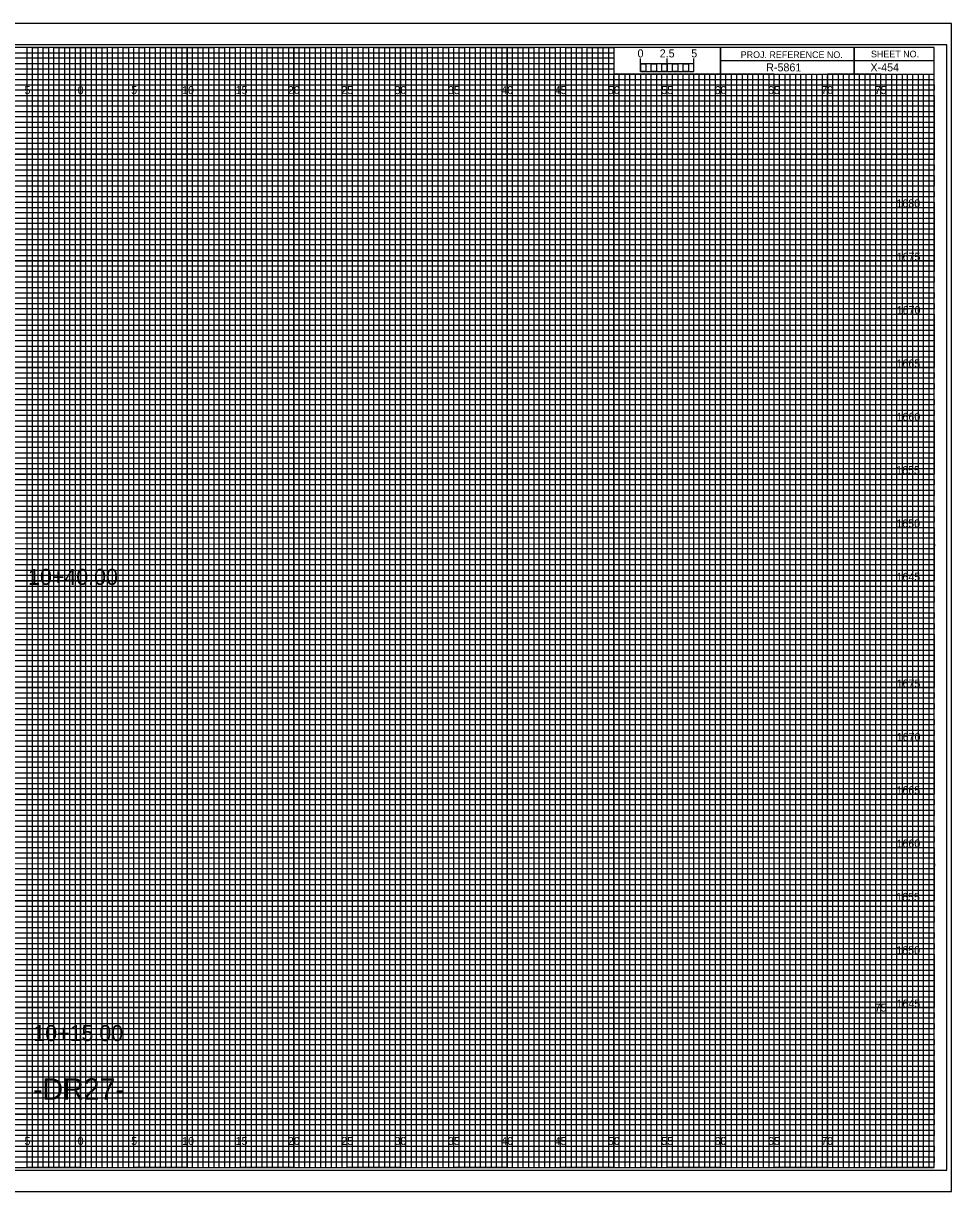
# Model space of a CAD drawing. Extents: x -7 to 162, y -2 to 217.
# Drawn here: x 74.6 to 161.7, y -2.3 to 107.3 of the extents above; entities that cross this region are included whole.
import ezdxf

# ---------------------------------------------------------------- set-up
doc = ezdxf.new("R2010")
doc.units = 0
for name, color, linetype in [('Prop Horizontal Alignment', 7, 'Continuous'), ('Prop XS Alignment Label', 7, 'Continuous'), ('Prop XS Bar Scale Labels', 7, 'Continuous'), ('Prop XS Gore Control Minimum', 7, 'Continuous'), ('Prop XS Project Number', 7, 'Continuous'), ('Prop XS Sheet Number', 7, 'Continuous'), ('Raster_Level_0', 7, 'Continuous'), ('Scratch_Level_3', 7, 'Continuous'), ('Sheet Cross Section CELL', 7, 'Continuous'), ('Sheet Cross Section Grid Middle CELL', 7, 'Continuous'), ('Sheet Cross Section Grid Minor 1 CELL', 7, 'Continuous'), ('Sheet Cross Section Grid Minor 2 CELL', 7, 'Continuous'), ('Sheet Cross Section Scale CELL', 7, 'Continuous'), ('Sheet Cutting Line CELL', 7, 'Continuous'), ('Sheet DOT Grid CELL', 7, 'Continuous'), ('Sheet Plot Border Inside CELL', 7, 'Continuous'), ('Sheet Plot Border Outside CELL', 7, 'Continuous')]:
    doc.layers.add(name, color=color, linetype=linetype)

msp = doc.modelspace()

# ---------------------------------------------------------------- linework, layer by layer
at = {"layer": 'Prop XS Gore Control Minimum'}
for p, q in [((75, 105), (70, 105)), ((75, 0), (75, 105)), ((85, 105), (80, 105)), ((80, 105), (80, 0)), ((85, 0), (85, 105)), ((95, 105), (90, 105)), ((90, 105), (90, 0)), ((95, 0), (95, 105)), ((105, 105), (100, 105)), ((100, 105), (100, 0)), ((105, 0), (105, 105)), ((115, 105), (110, 105)), ((110, 105), (110, 0)), ((115, 0), (115, 105)), ((125, 105), (120, 105)), ((120, 105), (120, 0)), ((125, 0), (125, 105)), ((130, 105), (130, 0)), ((135, 0), (135, 102.5)), ((145, 102.5), (140, 102.5)), ((140, 102.5), (140, 0)), ((145, 0), (145, 102.5)), ((155, 102.5), (150, 102.5)), ((150, 102.5), (150, 0)), ((155, 0), (155, 102.5)), ((80, 0), (75, 0)), ((90, 0), (85, 0)), ((100, 0), (95, 0)), ((110, 0), (105, 0)), ((120, 0), (115, 0)), ((130, 0), (125, 0)), ((140, 0), (135, 0)), ((150, 0), (145, 0)), ((160, 0), (155, 0)), ((160, 0), (160, 0))]:
    msp.add_line(p, q, dxfattribs=at)
for points in [[(0, 100), (160, 100), (160, 95), (0, 95)], [(0, 90), (160, 90), (160, 85), (0, 85)], [(0, 80), (160, 80), (160, 75), (0, 75)], [(0, 70), (160, 70), (160, 65), (0, 65)], [(0, 60), (160, 60), (160, 55), (0, 55)], [(0, 50), (160, 50), (160, 45), (0, 45)], [(0, 40), (160, 40), (160, 35), (0, 35)], [(0, 30), (160, 30), (160, 25), (0, 25)], [(0, 20), (160, 20), (160, 15), (0, 15)], [(0, 10), (160, 10), (160, 5), (0, 5)]]:
    msp.add_lwpolyline(points, dxfattribs=at)
at = {"layer": 'Sheet Cross Section CELL'}
for p, q in [((152.5, 105), (152.5, 102.5)), ((152.5, 102.5), (152.5, 105)), ((160, 103.75), (140, 103.75)), ((140, 103.75), (140, 102.5)), ((140, 102.5), (160, 102.5))]:
    msp.add_line(p, q, dxfattribs=at)
for points in [[(160, 105), (0, 105), (0, 0), (160, 0)], [(140, 105), (130, 105), (130, 102.52), (140, 102.52)], [(160, 105), (140, 105), (140, 102.5), (160, 102.5)]]:
    msp.add_lwpolyline(points, close=True, dxfattribs=at)
at = {"layer": 'Sheet Cross Section Grid Middle CELL'}
for points in [[(72.5, 0), (77.5, 0), (77.5, 105), (82.5, 105), (82.5, 0), (87.5, 0), (87.5, 105), (92.5, 105), (92.5, 0), (97.5, 0), (97.5, 105), (102.5, 105), (102.5, 0), (107.5, 0), (107.5, 105), (112.5, 105), (112.5, 0), (117.5, 0), (117.5, 105), (122.5, 105), (122.5, 0), (127.5, 0), (127.5, 105), (129.97, 105), (130, 105), (130, 102.5), (132.5, 102.5), (132.5, 0), (137.5, 0), (137.5, 102.5), (142.5, 102.5), (142.5, 0), (147.5, 0), (147.5, 102.5), (152.5, 102.5), (152.5, 0), (157.5, 0), (157.5, 102.5)], [(0, 102.5), (137.5, 102.5)], [(0, 92.5), (160, 92.5), (160, 97.5), (0, 97.5)], [(0, 82.5), (160, 82.5), (160, 87.5), (0, 87.5)], [(0, 72.5), (160, 72.5), (160, 77.5), (0, 77.5)], [(0, 62.5), (160, 62.5), (160, 67.5), (0, 67.5)], [(0, 52.5), (160, 52.5), (160, 57.5), (0, 57.5)], [(0, 42.5), (160, 42.5), (160, 47.5), (0, 47.5)], [(0, 32.5), (160, 32.5), (160, 37.5), (0, 37.5)], [(0, 22.5), (160, 22.5), (160, 27.5), (0, 27.5)], [(0, 12.5), (160, 12.5), (160, 17.5), (0, 17.5)], [(0, 2.5), (160, 2.5), (160, 7.5), (0, 7.5)]]:
    msp.add_lwpolyline(points, dxfattribs=at)
at = {"layer": 'Sheet Cross Section Grid Minor 1 CELL'}
for p, q in [((0, 104.5), (130, 104.5)), ((130, 104.5), (130, 103.99)), ((130, 103.99), (0, 103.99)), ((0, 103.5), (130, 103.5)), ((130, 102.95), (0, 102.95)), ((130, 103.5), (130, 102.95)), ((0, 102), (160, 102))]:
    msp.add_line(p, q, dxfattribs=at)
for points in [[(0, 101.5), (135, 101.5), (160, 101.5), (160, 101), (0, 101)], [(0, 100.5), (160, 100.5), (160, 99.5), (0, 99.5)], [(0, 99), (160, 99), (160, 98.5), (0, 98.49)], [(0, 98), (160, 98), (160, 97), (0, 97)], [(0, 96.5), (160, 96.5), (160, 96), (0, 96)], [(0, 95.5), (160, 95.5), (160, 94.5), (0, 94.5)], [(0, 94), (160, 94), (160, 93.5), (0, 93.5)], [(0, 93), (160, 93), (160, 92), (0, 92)], [(0, 91.5), (160, 91.5), (160, 91), (0, 91)], [(0, 90.5), (160, 90.5), (160, 89.5), (0, 89.5)], [(0, 89), (160, 89), (160, 88.5), (0, 88.5)], [(0, 88), (160, 88), (160, 86.98), (160, 86.5), (160, 86), (0, 86)], [(0, 87), (160, 87), (160, 86.5), (0, 86.5)], [(0, 85.5), (160, 85.5), (160, 84.5), (0, 84.52)], [(0, 84.52), (160, 84.5), (160, 84), (0, 84)], [(0, 83.5), (160, 83.5), (160, 83), (0, 83)], [(0, 82), (160, 82), (160, 81.5), (0, 81.5)], [(0, 81), (160, 81), (160, 80.5), (0, 80.5)], [(-0.04, 79.45), (160, 79.45), (160, 78.94), (-0.04, 78.94)], [(0, 78.5), (160, 78.5), (160, 78), (0, 78)], [(0, 77), (160, 77), (160, 76.5), (0, 76.5)], [(0, 76), (160, 76), (160, 75.5), (0, 75.5)], [(0, 74.5), (160, 74.5), (160, 74), (0, 74)], [(0, 73.5), (160, 73.5), (160, 73), (0, 73)], [(0, 72), (160, 72), (160, 71.5), (0, 71.5)], [(0, 71), (160, 71), (160, 70.5), (0, 70.5)], [(0, 69.5), (160, 69.5), (160, 68.99), (0, 69)], [(0, 68.5), (160, 68.5), (160, 68), (0, 68)], [(0, 67), (160, 67), (160, 66.5), (0, 66.5)], [(0, 66), (160, 66), (160, 65.5), (0, 65.5)], [(0, 64.5), (160, 64.5), (160, 64), (0, 64)], [(0, 63.5), (160, 63.5), (160, 63), (0, 63)], [(0, 62), (160, 62), (160, 61.5), (0, 61.5)], [(0, 61), (160, 61), (160, 60.5), (0, 60.5)], [(0, 59.5), (160, 59.5), (160, 59), (0, 59)], [(0, 58.5), (160.03, 58.45), (160, 58), (0, 58)], [(0, 57), (160, 57), (160, 56.5), (0, 56.5)], [(0, 56), (160, 56), (160, 55.5), (0, 55.5)], [(0, 54.5), (160, 54.5), (160, 54), (0, 54)], [(0, 53.5), (160, 53.5), (160, 53), (0, 53)], [(0, 52), (160, 52), (160, 51.5), (0, 51.5)], [(0, 51), (160, 51), (160, 50.5), (0, 50.5)], [(0, 49.5), (160, 49.5), (160, 49), (0, 49)], [(0, 48.5), (160, 48.5), (160, 48), (0, 48)], [(0, 47), (160, 47), (160, 46.5), (0, 46.5)], [(0, 46), (160, 46), (160, 45.5), (0, 45.5)], [(0, 44.5), (160, 44.5), (160, 44), (0, 44)], [(0, 43.5), (160, 43.5), (160, 43), (0, 43)], [(0, 42), (160, 42), (160, 41.5), (0, 41.5)], [(0, 41), (160, 41), (160, 40.5), (0, 40.5)], [(0, 39.5), (160, 39.5), (160, 38.99), (0, 39)], [(0, 38.5), (160, 38.5), (160, 38), (0, 38)], [(0, 37), (160, 37), (160, 36.5), (0, 36.5)], [(0, 36), (160, 36), (160, 35.5), (0, 35.5)], [(0, 34.5), (160, 34.5), (160, 34), (0, 34)], [(0, 33.5), (160, 33.5), (160, 33), (0, 33)], [(0, 32), (160, 32), (160, 31.5), (0, 31.5)], [(0, 31), (160, 31), (160, 30.5), (0, 30.5)], [(0, 29.5), (160, 29.5), (160, 29), (0, 29)], [(0, 28.5), (160.03, 28.46), (160, 28), (0, 28)], [(0, 27), (160, 27), (160, 26.5), (0, 26.5)], [(0, 26), (160, 26), (160, 25.5), (0, 25.5)], [(0, 24.5), (160, 24.5), (160, 24), (0, 24)], [(0, 23.5), (160, 23.5), (160, 23), (0, 23)], [(0, 22), (160, 22), (160, 21.5), (0, 21.5)], [(0, 21), (160, 21), (160, 20.5), (0, 20.5)], [(0, 19.5), (160, 19.5), (160, 19), (0, 19)], [(0, 18.5), (160, 18.5), (160, 18), (0, 18)], [(0, 17), (160, 17), (160, 16.5), (0, 16.5)], [(0, 16), (160, 16), (160, 15.5), (0, 15.5)], [(0, 14.5), (160, 14.5), (160, 14), (0, 14)], [(0, 13.5), (160, 13.5), (160, 13), (0, 13)], [(0, 12), (160, 12), (160, 11.5), (0, 11.5)], [(0, 11), (160, 11), (160, 10.5), (0, 10.5)], [(0, 9.5), (160, 9.5), (160, 9), (0, 9)], [(0, 8.5), (160, 8.5), (160, 8), (0, 8)], [(0, 7), (160, 7), (160, 6.5), (0, 6.5)], [(0, 6), (160, 6), (160, 5.5), (0, 5.5)], [(0, 4.5), (160, 4.5), (160, 4), (0, 4)], [(0, 3.5), (160, 3.5), (160, 3), (0, 3)], [(0, 2), (160, 2), (160, 1.5), (0, 1.5)], [(0, 1), (160, 1), (160, 0.5), (0, 0.5)]]:
    msp.add_lwpolyline(points, dxfattribs=at)
at = {"layer": 'Sheet Cross Section Grid Minor 2 CELL'}
for p, q in [((133.5, 102.5), (133, 102.5)), ((133, 102.5), (133, 0)), ((133.5, 0), (133.5, 102.5)), ((134.5, 102.5), (134, 102.5)), ((134, 102.5), (134, 0)), ((134.5, 0), (134.5, 102.5)), ((133, 0), (132.5, 0)), ((134, 0), (133.5, 0))]:
    msp.add_line(p, q, dxfattribs=at)
for points in [[(75, 0), (75.5, 0), (75.5, 105), (76, 105), (76, 0)], [(76, 0), (76.5, 0), (76.5, 105), (77, 105), (77, 0)], [(77.5, 0), (78, 0), (78, 105), (78.5, 105), (78.5, 0)], [(78.5, 0), (79, 0), (79, 105), (79.5, 105), (79.5, 0)], [(80, 0), (80.5, 0), (80.5, 105), (81, 105), (81, 0)], [(81, 0), (81.5, 0), (81.5, 105), (82, 105), (82, 0)], [(82.5, 0), (83, 0), (83, 105), (83.5, 105), (83.5, 0)], [(83.5, 0), (84, 0), (84, 105), (84.5, 105), (84.5, 0)], [(85, 0), (85.5, 0), (85.5, 105), (86, 105), (86, 0)], [(86, 0), (86.5, 0), (86.5, 105), (87, 105), (87, 0)], [(87.5, 0), (88, 0), (88, 105), (88.5, 105), (88.5, 0)], [(88.5, 0), (89, 0), (89, 105), (89.5, 105), (89.5, 0)], [(90, 0), (90.5, 0), (90.5, 105), (91, 105), (91, 0)], [(91, 0), (91.5, 0), (91.5, 105), (92, 105), (92, 0)], [(92.5, 0), (93, 0), (93, 105), (93.5, 105), (93.5, 0)], [(93.5, 0), (94, 0), (94, 105), (94.5, 105), (94.5, 0)], [(95, 0), (95.5, 0), (95.5, 105), (96, 105), (96, 0)], [(96, 0), (96.5, 0), (96.5, 105), (97, 105), (97, 0)], [(97.5, 0), (98, 0), (98, 105), (98.5, 105), (98.5, 0)], [(98.5, 0), (99, 0), (99, 105), (99.5, 105), (99.5, 0)], [(100, 0), (100.5, 0), (100.5, 105), (101, 105), (101, 0)], [(101, 0), (101.5, 0), (101.5, 105), (102, 105), (102, 0)], [(102.5, 0), (103, 0), (103, 105), (103.5, 105), (103.5, 0)], [(103.5, 0), (104, 0), (104, 105), (104.5, 105), (104.5, 0)], [(105, 0), (105.5, 0), (105.5, 105), (106, 105), (106, 0)], [(106, 0), (106.5, 0), (106.5, 105), (107, 105), (107, 0)], [(107.5, 0), (108, 0), (108, 105), (108.5, 105), (108.5, 0)], [(108.5, 0), (109, 0), (109, 105), (109.5, 105), (109.5, 0)], [(110, 0), (110.5, 0), (110.5, 105), (111, 105), (111, 0)], [(111, 0), (111.5, 0), (111.5, 105), (112, 105), (112, 0)], [(112.5, 0), (113, 0), (113, 105), (113.5, 105), (113.5, 0)], [(113.5, 0), (114, 0), (114, 105), (114.5, 105), (114.5, 0)], [(115, 0), (115.5, 0), (115.5, 105), (116, 105), (116, 0)], [(116, 0), (116.5, 0), (116.5, 105), (117, 105), (117, 0)], [(117.5, 0), (118, 0), (118, 105), (118.5, 105), (118.5, 0)], [(118.5, 0), (119, 0), (119, 105), (119.5, 105), (119.5, 0)], [(120, 0), (120.5, 0), (120.5, 105), (121, 105), (121, 0)], [(121, 0), (121.5, 0), (121.5, 105), (122, 105), (122, 0)], [(122.5, 0), (123, 0), (123, 105), (123.5, 105), (123.5, 0)], [(123.5, 0), (124, 0), (124, 105), (124.5, 105), (124.5, 0)], [(125, 0), (125.5, 0), (125.5, 105), (126, 105), (126, 0)], [(126, 0), (126.5, 0), (126.5, 105), (127, 105), (127, 0)], [(127.5, 0), (128, 0), (128, 105), (128.5, 105), (128.5, 0)], [(128.5, 0), (129, 0), (129, 105), (129.5, 105), (129.5, 0)], [(130, 0), (130.5, 0), (130.5, 102.5), (131.01, 102.5), (131.01, 0)], [(131, 0), (131.5, 0), (131.5, 102.5), (132, 102.5), (132, 0)], [(135, 0), (135.49, 0), (135.49, 102.5), (136, 102.5), (136, 0)], [(136, 0), (136.5, 0), (136.5, 102.5), (137.03, 102.5), (137.03, 0)], [(137.5, 0), (138, 0), (138, 102.5), (138.5, 102.5), (138.5, 0)], [(138.5, 0), (139, 0), (139, 102.5), (139.5, 102.5), (139.5, 0)], [(140, 0), (140.5, 0), (140.5, 102.5), (141, 102.5), (141, 0)], [(141, 0), (141.5, 0), (141.5, 102.5), (142, 102.5), (142, 0)], [(142.5, 0), (143, 0), (143, 102.5), (143.5, 102.5), (143.5, 0)], [(143.5, 0), (144, 0), (144, 102.5), (144.5, 102.5), (144.5, 0)], [(145, 0), (145.5, 0), (145.5, 102.5), (146, 102.5), (146, 0)], [(146, 0), (146.5, 0), (146.5, 102.5), (147, 102.5), (147, 0)], [(147.5, 0), (148, 0), (148, 102.5), (148.5, 102.5), (148.5, 0)], [(148.5, 0), (149, 0), (149, 102.5), (149.5, 102.5), (149.5, 0)], [(150, 0), (150.5, 0), (150.5, 102.5), (151, 102.5), (151, 0)], [(151, 0), (151.5, 0), (151.5, 102.5), (152, 102.5), (152, 0)], [(152.5, 0), (153, 0), (153, 102.5), (153.5, 102.5), (153.5, 0)], [(153.5, 0), (154, 0), (154, 102.5), (154.5, 102.5), (154.5, 0)], [(155, 0), (155.5, 0), (155.5, 102.5), (156, 102.5), (156, 0)], [(156, 0), (156.5, 0), (156.5, 102.5), (157, 102.5), (157, 0)], [(157.5, 0), (158, 0), (158, 102.5), (158.5, 102.5), (158.5, 0)], [(158.5, 0), (159, 0), (159, 102.5), (159.5, 102.5), (159.5, 0)]]:
    msp.add_lwpolyline(points, dxfattribs=at)
at = {"layer": 'Sheet Cross Section Scale CELL'}
for p, q in [((132.5, 102.75), (132.5, 103.95)), ((132.5, 103.45), (132.5, 103.95)), ((135, 102.75), (135, 103.95)), ((137.5, 102.75), (137.5, 103.95)), ((137.5, 103.45), (137.5, 103.95))]:
    msp.add_line(p, q, dxfattribs=at)
for points in [[(137.5, 103.45), (132.5, 103.45), (132.5, 102.75), (137.5, 102.75)], [(132.5, 103.45), (133, 103.45), (133, 102.75), (132.5, 102.75)], [(133.5, 103.45), (134, 103.45), (134, 102.75), (133.5, 102.75)], [(134.5, 103.45), (135, 103.45), (135, 102.75), (134.5, 102.75)], [(135.5, 103.45), (136, 103.45), (136, 102.75), (135.5, 102.75)], [(136.5, 103.45), (137, 103.45), (137, 102.75), (136.5, 102.75)]]:
    msp.add_lwpolyline(points, close=True, dxfattribs=at)
at = {"layer": 'Sheet Cutting Line CELL'}
for p, q in [((161.65, 107.25), (-6.7, 107.25)), ((-6.7, -2.25), (161.65, -2.25))]:
    msp.add_line(p, q, dxfattribs=at)
at = {"layer": 'Sheet DOT Grid CELL'}
for p, q in [((75, 0), (75, 105)), ((80, 0), (80, 105)), ((85, 0), (85, 105)), ((90, 0), (90, 105)), ((95, 0), (95, 105)), ((100, 0), (100, 105)), ((105, 0), (105, 105)), ((110, 0), (110, 105)), ((115, 0), (115, 105)), ((120, 0), (120, 105)), ((125, 0), (125, 105)), ((130, 0), (130, 102.34)), ((135, 0), (135, 102.34)), ((140, 0), (140, 102.34)), ((145, 0), (145, 102.34)), ((150, 0), (150, 102.34)), ((155, 0), (155, 102.34)), ((0, 100), (160, 100)), ((0, 95), (160, 95)), ((0, 90), (160, 90)), ((0, 85), (160, 85)), ((0, 80), (160, 80)), ((0, 75), (160, 75)), ((0, 70), (160, 70)), ((0, 65), (160, 65)), ((0, 60), (160, 60)), ((0, 55), (160, 55)), ((0, 50), (160, 50)), ((0, 45), (160, 45)), ((0, 40), (160, 40)), ((0, 35), (160, 35)), ((0, 30), (160, 30)), ((0, 25), (160, 25)), ((0, 20), (160, 20)), ((0, 15), (160, 15)), ((0, 10), (160, 10)), ((0, 5), (160, 5))]:
    msp.add_line(p, q, dxfattribs=at)
at = {"layer": 'Sheet Plot Border Inside CELL'}
msp.add_lwpolyline([(-5.4, -0.25), (161.2, -0.25), (161.2, 105.25), (-5.4, 105.25)], close=True, dxfattribs=at)
at = {"layer": 'Sheet Plot Border Outside CELL'}
msp.add_lwpolyline([(-6.7, -2.25), (161.65, -2.25), (161.65, 107.25), (-6.7, 107.25)], close=True, dxfattribs=at)

# ---------------------------------------------------------------- texts
at = {"layer": 'Prop Horizontal Alignment'}
for s, p in [('10+40.00', (75.08, 54.62)), ('10+15.00', (75.57, 11.86))]:
    msp.add_text(s, height=1.5, dxfattribs=at).set_placement(p)
at = {"layer": 'Prop XS Alignment Label'}
msp.add_text('-DR27-', height=2, dxfattribs=at).set_placement((75.54, 6.37))
at = {"layer": 'Prop XS Bar Scale Labels'}
for s, p in [('2.5', (134.29, 104.06)), ('5', (137.24, 104.06))]:
    msp.add_text(s, height=0.75, dxfattribs=at).set_placement(p)
at = {"layer": 'Prop XS Project Number'}
msp.add_text('R-5861', height=0.75, dxfattribs=at).set_placement((144.27, 102.75))
at = {"layer": 'Prop XS Sheet Number'}
msp.add_text('X-454', height=0.75, dxfattribs=at).set_placement((154.04, 102.75))
at = {"layer": 'Raster_Level_0'}
for s, p in [('5', (74.74, 100.62)), ('0', (79.73, 100.62)), ('0', (79.73, 100.62)), ('5', (84.74, 100.62)), ('10', (89.52, 100.62)), ('15', (94.53, 100.62)), ('20', (99.43, 100.62)), ('25', (104.44, 100.62)), ('30', (109.43, 100.62)), ('35', (114.44, 100.62)), ('40', (119.43, 100.62)), ('45', (124.44, 100.62)), ('50', (129.43, 100.62)), ('55', (134.44, 100.62)), ('60', (139.43, 100.62)), ('65', (144.44, 100.62)), ('70', (149.43, 100.62)), ('75', (154.44, 100.62)), ('75', (154.44, 14.62)), ('5', (74.74, 2.12)), ('0', (79.73, 2.12)), ('0', (79.73, 2.12)), ('5', (84.74, 2.12)), ('10', (89.52, 2.12)), ('15', (94.53, 2.12)), ('20', (99.43, 2.12)), ('25', (104.44, 2.12)), ('30', (109.43, 2.12)), ('35', (114.44, 2.12)), ('40', (119.43, 2.12)), ('45', (124.44, 2.12)), ('50', (129.43, 2.12)), ('55', (134.44, 2.12)), ('60', (139.43, 2.12)), ('65', (144.44, 2.12)), ('70', (149.43, 2.12))]:
    msp.add_text(s, height=0.75, dxfattribs=at).set_placement(p)
at = {"layer": 'Scratch_Level_3'}
for s, p in [('1680', (156.47, 90)), ('1675', (156.49, 85)), ('1670', (156.5, 80)), ('1665', (156.48, 75)), ('1660', (156.48, 70)), ('1655', (156.45, 65)), ('1650', (156.46, 60)), ('1645', (156.48, 55)), ('1675', (156.49, 45)), ('1670', (156.5, 40)), ('1665', (156.48, 35)), ('1660', (156.48, 30)), ('1655', (156.45, 25)), ('1650', (156.46, 20)), ('1645', (156.48, 15))]:
    msp.add_text(s, height=0.75, dxfattribs=at).set_placement(p)
at = {"layer": 'Sheet Cross Section CELL'}
for s, p in [('PROJ. REFERENCE NO.', (141.88, 104)), ('SHEET NO.', (154.09, 104.06))]:
    msp.add_text(s, height=0.625, dxfattribs=at).set_placement(p)
at = {"layer": 'Sheet Cross Section Scale CELL'}
msp.add_text('0', height=0.75, dxfattribs=at).set_placement((132.21, 104.06))

doc.saveas('drawing.dxf')
